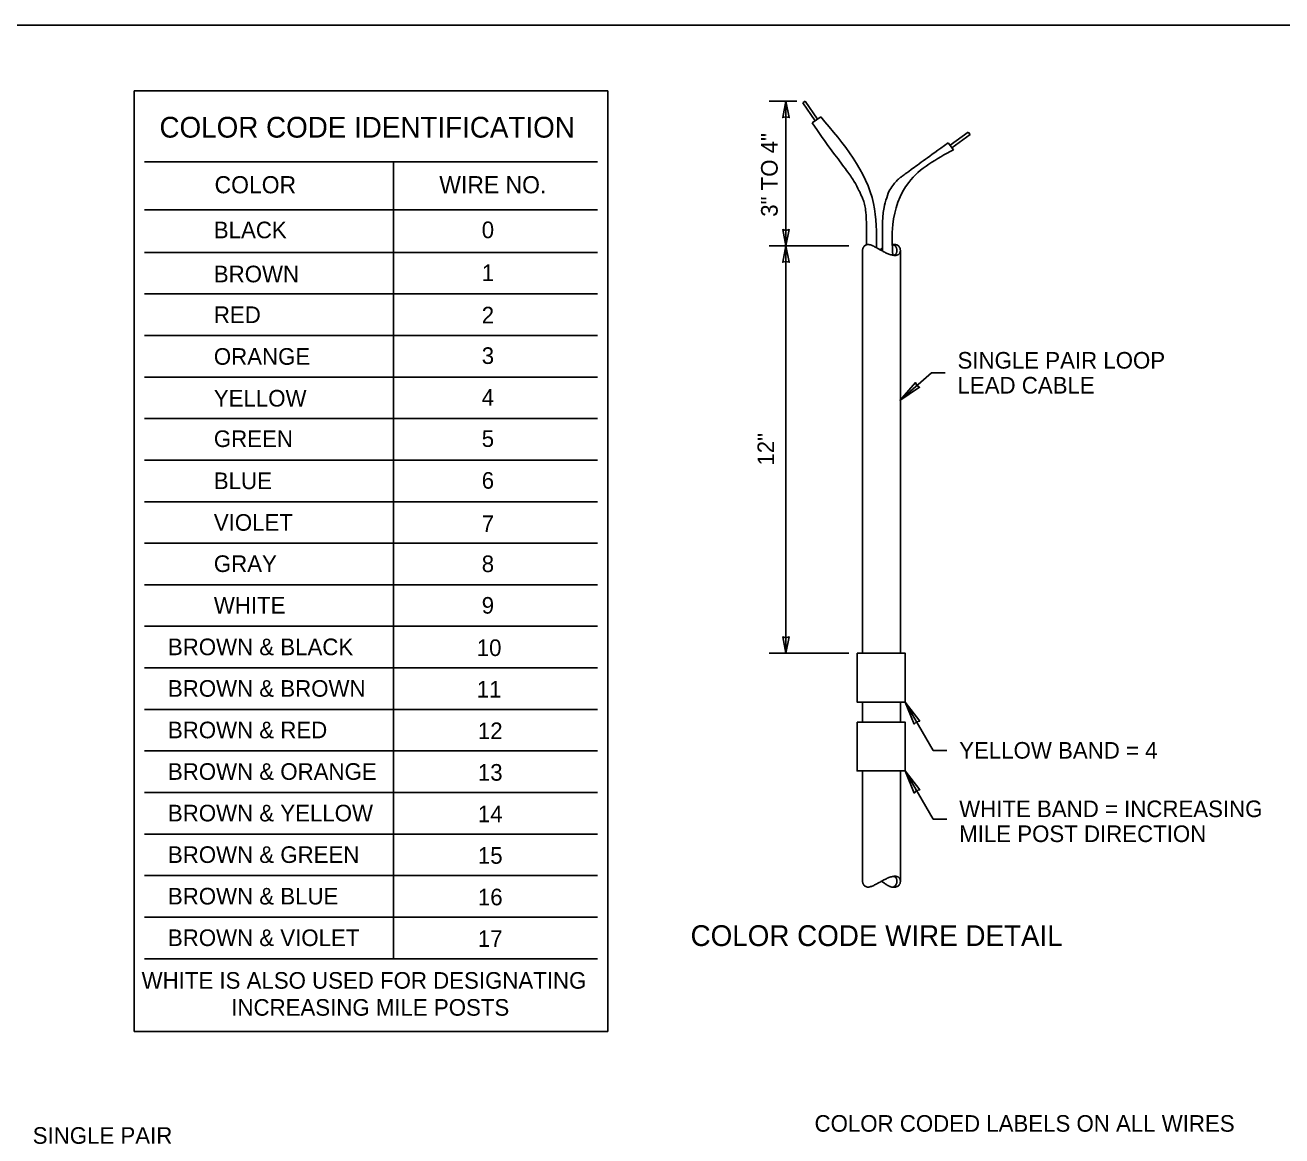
# Model space of a CAD drawing. Extents: x 99862 to 103151, y 100000 to 108076.
# Drawn here: x 101127 to 102337, y 107006 to 108076 of the extents above; entities that cross this region are included whole.
import ezdxf

# ---------------------------------------------------------------- set-up
doc = ezdxf.new("R2010")
doc.units = 0
for name, color, linetype in [('Level 1', 7, 'Continuous'), ('Level 15', 7, 'Continuous'), ('Level 20', 7, 'Continuous'), ('Level 3', 7, 'Continuous'), ('Level 30', 7, 'Continuous'), ('Level 32', 7, 'Continuous'), ('Level 33', 7, 'Continuous'), ('Level 34', 7, 'Continuous'), ('Level 40', 7, 'Continuous'), ('Level 50', 7, 'Continuous')]:
    doc.layers.add(name, color=color, linetype=linetype)

msp = doc.modelspace()

# ---------------------------------------------------------------- linework, layer by layer
at = {"layer": 'Level 1'}
msp.add_lwpolyline([(99862, 105999.5), (103151, 105999.5), (103151, 108075.5), (99862, 108075.5)], close=True, dxfattribs=at)
msp.add_lwpolyline([(99862, 105999.5), (103151, 105999.5), (103151, 108075.5), (99862, 108075.5)], close=True, dxfattribs=at)
at = {"layer": 'Level 15'}
for p, q in [((101843.5, 108002.2), (101870.3, 108002.2)), ((101859.7, 108002.2), (101859.7, 107862.9)), ((101843.5, 107862.9), (101920.2, 107862.9)), ((101859.7, 107862.9), (101859.7, 107470.7)), ((101969.2, 107714.1), (101999.6, 107740.8)), ((101999.6, 107740.8), (102012.8, 107740.8)), ((101843.5, 107470.7), (101920.2, 107470.7)), ((101974.4, 107423.8), (102001.2, 107377.3)), ((102001.2, 107377.3), (102014.4, 107377.3)), ((101974.4, 107357.5), (102001.2, 107311)), ((102001.2, 107311), (102014.4, 107311))]:
    msp.add_line(p, q, dxfattribs=at)
for points in [[(101859.7, 108002.2), (101856.6, 107986.5), (101859.7, 107987.2), (101862.8, 107986.5)], [(101859.7, 107862.9), (101856.6, 107878.6), (101859.7, 107877.9), (101862.8, 107878.6)], [(101859.7, 107862.9), (101856.6, 107847.2), (101859.7, 107847.9), (101862.8, 107847.2)], [(101969.2, 107714.1), (101988.3, 107726.9), (101985.5, 107728.5), (101984.3, 107731.4)], [(101859.7, 107470.7), (101856.6, 107486.5), (101859.7, 107485.7), (101862.8, 107486.5)], [(101974.4, 107423.8), (101988.4, 107405.5), (101985.3, 107404.9), (101983.2, 107402.5)], [(101974.4, 107357.5), (101983.2, 107336.2), (101985.3, 107338.6), (101988.4, 107339.2)]]:
    msp.add_lwpolyline(points, close=True, dxfattribs=at)
at = {"layer": 'Level 3'}
for p, q in [((101949.6, 107858.5), (101949.6, 107858.5)), ((101963.9, 107853.2), (101963.9, 107853.2))]:
    msp.add_line(p, q, dxfattribs=at)
msp.add_open_spline([(101949.6, 107858.5), (101949.6, 107858.5), (101949.6, 107858.5), (101949.6, 107858.5)], degree=2, dxfattribs=at)
at = {"layer": 'Level 30'}
for p, q in [((101875.9, 108000.6), (101878.2, 108002.4)), ((101878.2, 108002.4), (101890.1, 107985.1)), ((101887.7, 107983.5), (101875.9, 108000.6)), ((101893.1, 107987.3), (101884.9, 107981.5)), ((102017.6, 107959.8), (102035.1, 107972.5)), ((102036.8, 107970.2), (102019.3, 107957.4)), ((102035.1, 107972.5), (102036.8, 107970.2)), ((102015.8, 107962.3), (102020.8, 107955.4)), ((101933.4, 107858.5), (101933.4, 107470.7)), ((101969.9, 107470.7), (101969.9, 107858.5)), ((101933.4, 107423.6), (101933.4, 107404.4)), ((101969.9, 107404.4), (101969.9, 107423.6)), ((101933.4, 107357.1), (101933.4, 107251.6)), ((101969.9, 107251.6), (101969.9, 107357.4)), ((101964.5, 107256.1), (101964.5, 107256.1)), ((101951.6, 107251.3), (101951.6, 107251.3))]:
    msp.add_line(p, q, dxfattribs=at)
msp.add_lwpolyline([(101962.7, 107245.6), (101964.5, 107245.6)], dxfattribs=at)
for points, degree in [([(101937.1, 107864), (101937.4, 107880.6), (101936.7, 107895.3), (101936.1, 107899.9), (101934.3, 107906.3), (101933.5, 107908.5), (101931.7, 107912.8), (101930.7, 107915), (101925.2, 107925.7), (101919.2, 107934.1), (101906.4, 107951.2), (101899.6, 107959.8), (101884.9, 107981.5)], 3), ([(101952.6, 107857.8), (101952.6, 107864), (101952.6, 107871.4), (101952.6, 107878.8), (101952.6, 107882.6), (101952.6, 107883.9), (101952.7, 107886.7), (101952.7, 107888.1), (101953.2, 107895.2), (101954.1, 107901.1), (101957.5, 107912.6), (101960.1, 107918.2), (101964.9, 107924.2), (101965.9, 107925.3), (101967.6, 107927), (101968.2, 107927.5), (101969.1, 107928.3), (101969.4, 107928.5), (101970, 107929), (101970.4, 107929.3), (101972.7, 107930.9), (101978.8, 107935.4), (101993.2, 107945.8), (102005.4, 107954.8), (102015.8, 107962.3)], 3), ([(101933.4, 107858.5), (101933.4, 107858.7), (101933.4, 107859.1), (101933.5, 107859.7), (101933.7, 107860.6), (101934.1, 107861.4), (101934.6, 107862.2), (101935.3, 107862.9), (101936.2, 107863.6), (101937.3, 107864.1), (101938.2, 107864.2), (101938.7, 107864.2)], 3), ([(101964.5, 107864.2), (101965, 107864.2), (101965.9, 107864.1), (101967, 107863.6), (101967.9, 107862.9), (101968.6, 107862.2), (101969.1, 107861.4), (101969.5, 107860.6), (101969.7, 107859.7), (101969.8, 107858.9), (101969.8, 107858.1), (101969.7, 107857.3), (101969.4, 107856.5), (101969, 107855.7), (101968.4, 107855), (101967.6, 107854.4), (101966.6, 107854), (101965.3, 107853.8), (101963.8, 107853.8), (101962.1, 107854), (101960.5, 107854.4), (101958.8, 107855), (101957.2, 107855.7), (101955.6, 107856.4), (101954, 107857.2), (101952.5, 107858.1), (101951, 107858.9), (101949.5, 107859.7), (101948, 107860.6), (101946.5, 107861.4), (101945, 107862.2), (101943.4, 107862.9), (101941.9, 107863.6), (101940.3, 107864.1), (101939.2, 107864.2), (101938.7, 107864.2)], 3), ([(101952.5, 107860.9), (101952.4, 107860.8), (101951.8, 107860.4), (101951.1, 107859.9), (101950.5, 107859.5), (101950.3, 107859.4)], 3), ([(101963.1, 107864.1), (101963.9, 107863.7), (101964.3, 107863.4), (101964.9, 107862.9), (101965.5, 107862.2), (101965.9, 107861.4), (101966.2, 107860.6), (101966.4, 107859.7), (101966.5, 107858.9), (101966.5, 107858.1), (101966.4, 107857.3), (101966.2, 107856.5), (101965.8, 107855.7), (101965.3, 107855), (101964.7, 107854.4), (101963.9, 107854.1), (101963.4, 107853.9), (101963.1, 107853.8)], 3), ([(101964.5, 107245.6), (101965, 107245.6), (101965.9, 107245.8), (101967, 107246.3), (101967.9, 107246.9), (101968.6, 107247.7), (101969.1, 107248.4), (101969.5, 107249.2), (101969.7, 107250.1), (101969.8, 107250.9), (101969.8, 107251.8), (101969.7, 107252.6), (101969.4, 107253.4), (101969, 107254.1), (101968.4, 107254.8), (101967.6, 107255.4), (101966.6, 107255.8), (101965.3, 107256.1), (101963.8, 107256.1), (101962.2, 107255.9), (101960.5, 107255.4), (101958.8, 107254.8), (101957.2, 107254.1), (101955.6, 107253.4), (101954, 107252.6), (101952.5, 107251.8), (101951, 107250.9), (101949.5, 107250.1), (101948, 107249.3), (101946.5, 107248.4), (101945, 107247.7), (101943.5, 107246.9), (101941.9, 107246.3), (101940.3, 107245.8), (101939.3, 107245.6), (101938.8, 107245.6)], 3), ([(101962.9, 107245.6), (101963.9, 107246.1), (101964.3, 107246.4), (101964.9, 107246.9), (101965.5, 107247.7), (101965.9, 107248.4), (101966.2, 107249.2), (101966.4, 107250.1), (101966.5, 107250.9), (101966.5, 107251.8), (101966.4, 107252.6), (101966.2, 107253.4), (101965.8, 107254.1), (101965.3, 107254.8), (101964.7, 107255.4), (101963.9, 107255.8), (101963.4, 107255.9), (101963.1, 107256)], 3), ([(101933.4, 107251.3), (101933.4, 107251.2), (101933.4, 107250.8), (101933.5, 107250.1), (101933.8, 107249.3), (101934.1, 107248.4), (101934.6, 107247.7), (101935.3, 107246.9), (101936.2, 107246.3), (101937.3, 107245.8), (101938.2, 107245.6), (101938.8, 107245.6)], 3), ([(101951.6, 107251.3), (101951.6, 107251.3), (101951.6, 107251.3), (101951.6, 107251.3)], 2), ([(101955.7, 107248.5), (101955.4, 107248.7), (101954.6, 107249.3), (101953.4, 107250.1), (101952.4, 107250.8), (101951.8, 107251.2), (101951.6, 107251.3)], 3), ([(101958.2, 107247), (101958.1, 107247), (101957.6, 107247.2), (101956.7, 107247.8), (101955.9, 107248.3), (101955.5, 107248.6), (101955.5, 107248.6)], 3), ([(101961.1, 107245.7), (101961.1, 107245.8), (101960.5, 107245.9), (101959.6, 107246.3), (101958.7, 107246.7), (101958.2, 107247), (101958.2, 107247)], 3), ([(101962.7, 107245.6), (101962.2, 107245.6), (101961.7, 107245.7), (101961.2, 107245.7), (101961.1, 107245.7)], 3)]:
    msp.add_open_spline(points, degree=degree, dxfattribs=at)
for points in [[(101946.8, 107861.1), (101944, 107903.7), (101893.1, 107987.3)], [(102020.8, 107955.4), (101977.8, 107924.1), (101962.5, 107883.4), (101962.5, 107853.9)]]:
    msp.add_spline(points, degree=3, dxfattribs=at)
at = {"layer": 'Level 32'}
msp.add_lwpolyline([(101928.2, 107470.7), (101974.4, 107470.7), (101974.4, 107423.8), (101928.2, 107423.8)], close=True, dxfattribs=at)
at = {"layer": 'Level 33'}
for points in [[(101928.2, 107470.7), (101928.2, 107423.8), (101974.4, 107423.8), (101974.4, 107470.7), (101928.2, 107470.7)], [(101928.2, 107404.4), (101928.2, 107357.5), (101974.4, 107357.5), (101974.4, 107404.4), (101928.2, 107404.4)]]:
    msp.add_lwpolyline(points, dxfattribs=at)
msp.add_lwpolyline([(101928.2, 107404.4), (101974.4, 107404.4), (101974.4, 107357.5), (101928.2, 107357.5)], close=True, dxfattribs=at)
at = {"layer": 'Level 34'}
msp.add_lwpolyline([(101963, 107864.2), (101964.5, 107864.2)], dxfattribs=at)
at = {"layer": 'Level 40'}
for p, q in [((101232.5, 107106.7), (101232.5, 108012.1)), ((101232.5, 108012.1), (101688.2, 108012.1)), ((101688.2, 108012.1), (101688.2, 107106.7)), ((101242.5, 107944), (101678.2, 107944)), ((101482, 107944), (101482, 107176.7)), ((101242.5, 107176.7), (101678.2, 107176.7)), ((101232.5, 107106.7), (101688.2, 107106.7))]:
    msp.add_line(p, q, dxfattribs=at)
at = {"layer": 'Level 50'}
for p, q in [((101242.5, 107897.6), (101678.2, 107897.6)), ((101242.5, 107856.7), (101678.2, 107856.7)), ((101242.5, 107816.7), (101678.2, 107816.7)), ((101242.5, 107776.7), (101678.2, 107776.7)), ((101242.5, 107736.7), (101678.2, 107736.7)), ((101242.5, 107696.7), (101678.2, 107696.7)), ((101242.5, 107656.7), (101678.2, 107656.7)), ((101242.5, 107616.7), (101678.2, 107616.7)), ((101242.5, 107576.7), (101678.2, 107576.7)), ((101242.5, 107536.7), (101678.2, 107536.7)), ((101242.5, 107496.7), (101678.2, 107496.7)), ((101242.5, 107456.7), (101678.2, 107456.7)), ((101242.5, 107416.7), (101678.2, 107416.7)), ((101242.5, 107376.7), (101678.2, 107376.7)), ((101242.5, 107336.7), (101678.2, 107336.7)), ((101242.5, 107296.7), (101678.2, 107296.7)), ((101242.5, 107256.7), (101678.2, 107256.7)), ((101242.5, 107256.7), (101678.2, 107256.7)), ((101242.5, 107216.7), (101678.2, 107216.7))]:
    msp.add_line(p, q, dxfattribs=at)

# ---------------------------------------------------------------- texts
at = {"layer": 'Level 20'}
for s, height, rotation, p in [('COLOR CODE IDENTIFICATION', 20, 360, (101256.8, 107967.2)), ('3" TO 4"', 16, 90, (101851.7, 107891)), ('SINGLE PAIR LOOP', 16, 360, (102024.8, 107744.8)), ('LEAD CABLE', 16, 360, (102024.8, 107720.8)), ('12"', 16, 90, (101848.3, 107651.4)), ('YELLOW BAND = 4', 16, 360, (102026.4, 107369.3)), ('WHITE BAND = INCREASING ', 16, 360, (102026.4, 107313)), ('MILE POST DIRECTION', 16, 360, (102026.4, 107289)), ('WHITE IS ALSO USED FOR DESIGNATING ', 16, 360, (101239.6, 107147.8)), ('INCREASING MILE POSTS', 16, 360, (101325.9, 107121.8))]:
    msp.add_text(s, height=height, rotation=rotation, dxfattribs=at).set_placement(p)
for s, height, p in [('COLOR ', 16.5, (101309.8, 107913.6)), ('WIRE NO.', 16.5, (101526.1, 107913.6)), ('BLACK  ', 16, (101309.1, 107870.3)), ('0', 16, (101566.9, 107870.4)), ('BROWN  ', 16, (101309.1, 107827.9)), ('1', 16, (101566.9, 107829.1)), ('RED ', 16, (101309.1, 107788.7)), ('2', 16, (101566.9, 107788.3)), ('ORANGE ', 16, (101309.1, 107748.5)), ('3', 16, (101566.9, 107749.3)), ('YELLOW ', 16, (101309.1, 107708.3)), ('4', 16, (101566.9, 107709.1)), ('GREEN ', 16, (101309.1, 107669.3)), ('5', 16, (101566.9, 107669.4)), ('BLUE ', 16, (101309.1, 107628.8)), ('6', 16, (101566.9, 107629.2)), ('VIOLET ', 16, (101309.1, 107588.7)), ('7', 16, (101566.9, 107587.5)), ('GRAY ', 16, (101309.1, 107549)), ('8', 16, (101566.9, 107548.9)), ('WHITE', 16, (101309.1, 107509)), ('9', 16, (101566.9, 107508.9)), ('BROWN & BLACK  ', 16, (101264.9, 107468.9)), ('10', 16, (101562.1, 107468.1)), ('BROWN & BROWN  ', 16, (101264.9, 107428.9)), ('11', 16, (101562.1, 107428.1)), ('BROWN & RED  ', 16, (101264.9, 107388.9)), ('12', 16, (101563.2, 107388.1)), ('BROWN & ORANGE  ', 16, (101264.9, 107348.9)), ('13', 16, (101563.2, 107348.1)), ('BROWN & YELLOW  ', 16, (101264.9, 107308.9)), ('14', 16, (101563.2, 107308.1)), ('BROWN & GREEN  ', 16, (101264.9, 107268.9)), ('15', 16, (101563.2, 107268.1)), ('BROWN & BLUE  ', 16, (101264.9, 107228.9)), ('16', 16, (101563.2, 107228.1)), ('BROWN & VIOLET  ', 16, (101264.9, 107188.9)), ('17', 16, (101563.2, 107188.1)), ('COLOR CODE WIRE DETAIL', 20, (101767.9, 107188.9)), ('COLOR CODED LABELS ON ALL WIRES', 16, (101887.2, 107010.1)), ('SINGLE PAIR', 16, (101134.8, 106998.5))]:
    msp.add_text(s, height=height, dxfattribs=at).set_placement(p)

doc.saveas('drawing.dxf')
